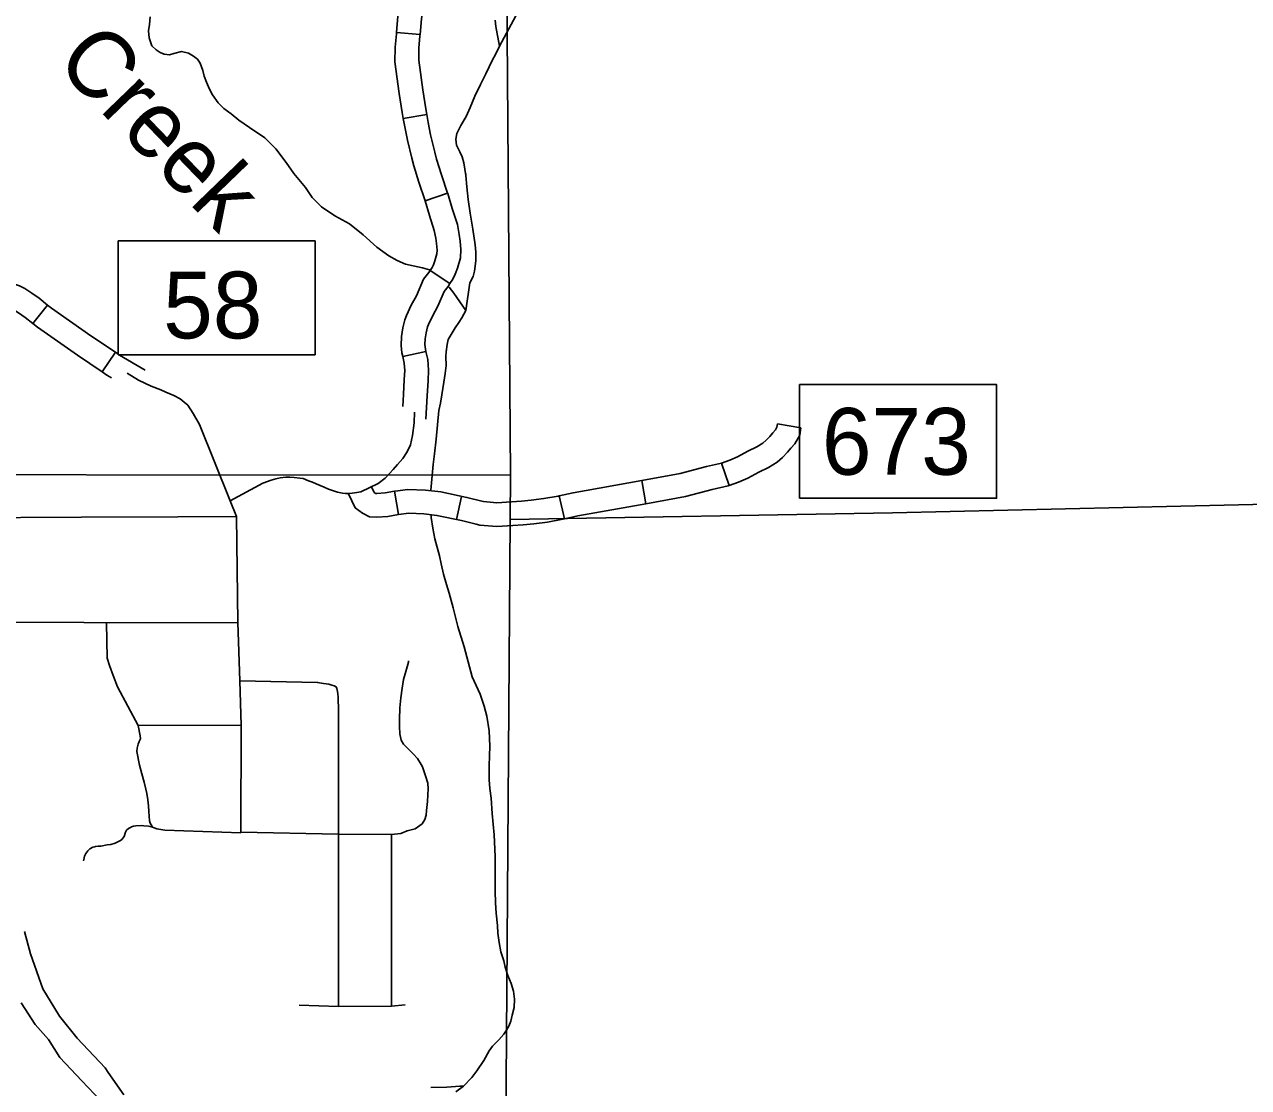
# Model space of a CAD drawing. Extents: x -492261 to -432772, y 1441225 to 1452922.
# Drawn here: x -463423.9 to -463202.9, y 1451379.2 to 1451571.3 of the extents above; entities that cross this region are included whole.
import ezdxf

# ---------------------------------------------------------------- set-up
doc = ezdxf.new("R2010")
doc.units = 0
doc.layers.add('Default', color=7, linetype='Continuous')

msp = doc.modelspace()

# ---------------------------------------------------------------- linework, layer by layer
at = {"layer": 'Default'}
for p, q in [((-463356.77, 1451569.8), (-463352.5, 1451569.45)), ((-463355.53, 1451554.3), (-463351.3, 1451555.02)), ((-463351.59, 1451539.42), (-463347.52, 1451540.77)), ((-463350.66, 1451526.83), (-463347.1, 1451524.46)), ((-463422.45, 1451517.23), (-463419.76, 1451520.57)), ((-463409.93, 1451508.5), (-463407.53, 1451512.05)), ((-463355.62, 1451511.27), (-463351.44, 1451512.2)), ((-463287.93, 1451499.1), (-463283.7, 1451498.41)), ((-463298.05, 1451492.05), (-463296.65, 1451488)), ((-463312.45, 1451488.91), (-463311.7, 1451484.7)), ((-463357.09, 1451486.95), (-463356.39, 1451482.72)), ((-463344.99, 1451486.02), (-463345.89, 1451481.83)), ((-463327.37, 1451486.12), (-463326.43, 1451481.94))]:
    msp.add_line(p, q, dxfattribs=at)
for points in [[(-463339.09, 1451740.72), (-463337.5, 1451641.25), (-463337.22, 1451633.29), (-463336.18, 1451489.83), (-463336.25, 1451481.82), (-463337.26, 1451337.74), (-463337.04, 1451330.58), (-463339.5, 1451167.68)], [(-463352.57, 1451584.76), (-463353.12, 1451583.25), (-463353.82, 1451581.65), (-463354.9, 1451579.19), (-463355.69, 1451577.12), (-463356.24, 1451574.87), (-463356.53, 1451572.75), (-463356.77, 1451569.8)], [(-463348.55, 1451583.28), (-463349.14, 1451581.66), (-463349.89, 1451579.93), (-463350.93, 1451577.56), (-463351.59, 1451575.84), (-463352.02, 1451574.07), (-463352.26, 1451572.29), (-463352.5, 1451569.45)], [(-463346.02, 1451550.55), (-463345.85, 1451551.57), (-463345.12, 1451553), (-463344.17, 1451554.67), (-463343.45, 1451556.28), (-463342.61, 1451558.35), (-463341.61, 1451560.42), (-463340.6, 1451562.38), (-463340.04, 1451563.65), (-463339.54, 1451564.62), (-463338.76, 1451566.12), (-463338.14, 1451567.33), (-463335.18, 1451572.85), (-463333.61, 1451575.22), (-463331.63, 1451577.53), (-463330, 1451579.09), (-463328.75, 1451579.96), (-463326.82, 1451580.79), (-463324.37, 1451581.22), (-463322.1, 1451581.76), (-463320.22, 1451582.01)], [(-463350.81, 1451526.94), (-463352.04, 1451527.3), (-463353.76, 1451527.68), (-463355.13, 1451527.95), (-463356.62, 1451528.62), (-463358.11, 1451529.46), (-463360.29, 1451531.03), (-463362.77, 1451533.3), (-463365.24, 1451535.27), (-463367.88, 1451536.73), (-463370.29, 1451538.3), (-463371.97, 1451540), (-463373.18, 1451541.82), (-463375.32, 1451544.37), (-463376.71, 1451546.35), (-463378.56, 1451548.79), (-463380.52, 1451550.77), (-463383.33, 1451552.69), (-463385.23, 1451553.98), (-463386.61, 1451555.11), (-463387.93, 1451556.07), (-463388.97, 1451557.14), (-463390.01, 1451558.56), (-463390.53, 1451559.58), (-463391.06, 1451560.84), (-463391.47, 1451561.92), (-463391.71, 1451562.95), (-463392.24, 1451564.26), (-463392.7, 1451564.99), (-463393.39, 1451565.56), (-463394.31, 1451566.12), (-463395.57, 1451566.39), (-463396.99, 1451566.03), (-463397.73, 1451565.79), (-463398.7, 1451565.9), (-463399.44, 1451566.23), (-463400.19, 1451566.68), (-463400.94, 1451567.42), (-463401.41, 1451568.84), (-463401.54, 1451570.1), (-463401.38, 1451571.25), (-463401.22, 1451572.68)], [(-463338.14, 1451567.33), (-463338.81, 1451570.93), (-463338.93, 1451572.07)], [(-463356.77, 1451569.8), (-463356.78, 1451569.61), (-463356.99, 1451567.19), (-463357.03, 1451564.55), (-463356.26, 1451558.83), (-463355.71, 1451555.36), (-463355.53, 1451554.3)], [(-463352.5, 1451569.45), (-463352.51, 1451569.25), (-463352.71, 1451566.98), (-463352.74, 1451564.81), (-463352.02, 1451559.45), (-463351.48, 1451556.06), (-463351.3, 1451555.02)], [(-463351.3, 1451555.02), (-463351.06, 1451553.59), (-463350.6, 1451551.33), (-463349.84, 1451548.2), (-463349.5, 1451546.94), (-463348.63, 1451544.09), (-463347.52, 1451540.77)], [(-463355.53, 1451554.3), (-463355.27, 1451552.8), (-463354.78, 1451550.39), (-463353.99, 1451547.13), (-463353.62, 1451545.76), (-463352.71, 1451542.79), (-463351.59, 1451539.42)], [(-463346.02, 1451550.55), (-463345.93, 1451549.49), (-463345.34, 1451548.25), (-463344.89, 1451547.36), (-463344.59, 1451546.26), (-463344.24, 1451544.02)], [(-463342.53, 1451531.45), (-463342.94, 1451534.31), (-463343.43, 1451537.16), (-463343.8, 1451539.68), (-463344.05, 1451541.96), (-463344.24, 1451544.02), (-463344.26, 1451544.27)], [(-463351.59, 1451539.43), (-463350.77, 1451536.76), (-463349.92, 1451534.08), (-463349.66, 1451532.69), (-463349.55, 1451531.7), (-463349.43, 1451530.5), (-463349.46, 1451529.81), (-463349.81, 1451528.57), (-463350.08, 1451527.83), (-463350.3, 1451527.37), (-463350.66, 1451526.83)], [(-463347.52, 1451540.77), (-463347.51, 1451540.74), (-463346.68, 1451538.04), (-463345.76, 1451535.13), (-463345.42, 1451533.33), (-463345.28, 1451532.15), (-463345.14, 1451530.61), (-463345.2, 1451529.12), (-463345.73, 1451527.26), (-463346.13, 1451526.16), (-463346.57, 1451525.24), (-463347.1, 1451524.46)], [(-463407.02, 1451511.61), (-463371.45, 1451511.61), (-463371.45, 1451532.16), (-463407.02, 1451532.16), (-463407.02, 1451511.61)], [(-463343.53, 1451524.6), (-463342.9, 1451525.74), (-463342.65, 1451526.69), (-463342.45, 1451528.57), (-463342.4, 1451530.11), (-463342.53, 1451531.45)], [(-463350.66, 1451526.83), (-463350.9, 1451526.48), (-463351.87, 1451525.29), (-463353.17, 1451522.24), (-463354.1, 1451520.54), (-463354.96, 1451518.71), (-463355.24, 1451517.9), (-463355.62, 1451516.45), (-463355.87, 1451514.9), (-463355.93, 1451513.29), (-463355.77, 1451511.93), (-463355.62, 1451511.27)], [(-463435.27, 1451524.75), (-463433.19, 1451524.91), (-463430.62, 1451524.94), (-463429.38, 1451524.89), (-463427.27, 1451524.73), (-463425.94, 1451524.39), (-463424.87, 1451524.05), (-463423.91, 1451523.58), (-463422.64, 1451522.71), (-463421.31, 1451521.82), (-463419.76, 1451520.57)], [(-463347.1, 1451524.46), (-463347.44, 1451523.94), (-463348.16, 1451523.05), (-463349.31, 1451520.36), (-463350.28, 1451518.6), (-463350.98, 1451517.09), (-463351.14, 1451516.64), (-463351.42, 1451515.56), (-463351.6, 1451514.48), (-463351.63, 1451513.46), (-463351.54, 1451512.64), (-463351.44, 1451512.2)], [(-463350.54, 1451487.11), (-463350.54, 1451487.15), (-463350.34, 1451489.78), (-463350.13, 1451491.79), (-463349.87, 1451493.68), (-463349.61, 1451496.37), (-463349.09, 1451501.53), (-463348.82, 1451502.85), (-463348.55, 1451504.39), (-463348.18, 1451506.63), (-463347.97, 1451508.23), (-463347.81, 1451509.67), (-463347.83, 1451511.27), (-463347.78, 1451512.13), (-463347.62, 1451513.44), (-463347.4, 1451514.36), (-463346.17, 1451516.49), (-463345.49, 1451517.41), (-463344.93, 1451518.28), (-463344.21, 1451519.6), (-463343.53, 1451524.6)], [(-463344.21, 1451519.6), (-463346.41, 1451522.73), (-463347.27, 1451523.81)], [(-463434.93, 1451520.48), (-463433, 1451520.63), (-463430.67, 1451520.66), (-463429.63, 1451520.62), (-463427.97, 1451520.48), (-463427.12, 1451520.27), (-463426.48, 1451520.06), (-463426.07, 1451519.86), (-463425.04, 1451519.16), (-463423.84, 1451518.36), (-463422.45, 1451517.23)], [(-463419.76, 1451520.57), (-463419.05, 1451520), (-463411.94, 1451515.04), (-463407.53, 1451512.05)], [(-463422.45, 1451517.23), (-463421.62, 1451516.57), (-463414.36, 1451511.51), (-463409.93, 1451508.5)], [(-463407.53, 1451512.05), (-463406.78, 1451511.54), (-463402.13, 1451508.81)], [(-463355.62, 1451511.27), (-463355.36, 1451510.08), (-463355.25, 1451508.77), (-463355.34, 1451507.14), (-463355.48, 1451504.4), (-463355.6, 1451502.24)], [(-463351.44, 1451512.2), (-463351.11, 1451510.73), (-463350.96, 1451508.83), (-463351.06, 1451506.92), (-463351.2, 1451504.17), (-463351.44, 1451499.99)], [(-463409.93, 1451508.5), (-463409.07, 1451507.91), (-463408.22, 1451507.42)], [(-463405.41, 1451508.25), (-463403.33, 1451507.03), (-463401.04, 1451505.91), (-463399.32, 1451505.25), (-463398.41, 1451504.86), (-463396.97, 1451504.24), (-463395.83, 1451503.63), (-463395.08, 1451503.06), (-463394.45, 1451502.5), (-463393.46, 1451501.02), (-463392.36, 1451499.03), (-463386.79, 1451485.19), (-463385.68, 1451482.4), (-463385.42, 1451463.24), (-463385.03, 1451452.72), (-463384.83, 1451444.71), (-463384.86, 1451425.34)], [(-463283.94, 1451485.68), (-463248.37, 1451485.68), (-463248.37, 1451506.23), (-463283.94, 1451506.23), (-463283.94, 1451485.68)], [(-463386.79, 1451485.19), (-463380.9, 1451488.41), (-463379.42, 1451488.94), (-463378.57, 1451489.18), (-463377.77, 1451489.36), (-463376.74, 1451489.48), (-463376, 1451489.49), (-463375.26, 1451489.44), (-463374.23, 1451489.34), (-463373.6, 1451489.23), (-463372.63, 1451488.84), (-463371.94, 1451488.57), (-463371.26, 1451488.29), (-463369.82, 1451487.68), (-463369.02, 1451487.34), (-463368.16, 1451487.01), (-463367.42, 1451486.79), (-463366.5, 1451486.63), (-463365.99, 1451486.57), (-463365.53, 1451486.52), (-463364.79, 1451486.59), (-463363.94, 1451486.71), (-463363.2, 1451486.84), (-463360.08, 1451488.36), (-463358.83, 1451489.29), (-463357.37, 1451490.85), (-463356.58, 1451491.77), (-463355.62, 1451492.87), (-463354.95, 1451493.91), (-463354.5, 1451494.66), (-463354.22, 1451495.35), (-463353.84, 1451497.01), (-463353.58, 1451499.3), (-463353.5, 1451501.25)], [(-463287.93, 1451499.1), (-463288.03, 1451498.51), (-463288.28, 1451498.06), (-463288.79, 1451497.5), (-463289.32, 1451496.84), (-463289.99, 1451496.16), (-463290.58, 1451495.63), (-463291.64, 1451494.97), (-463293.28, 1451494.18), (-463295.17, 1451493.15), (-463296.54, 1451492.58), (-463298.05, 1451492.05)], [(-463283.7, 1451498.41), (-463283.92, 1451497.05), (-463284.79, 1451495.54), (-463285.52, 1451494.72), (-463286.12, 1451493.99), (-463287.03, 1451493.05), (-463288.02, 1451492.19), (-463289.57, 1451491.21), (-463291.33, 1451490.37), (-463293.3, 1451489.29), (-463295, 1451488.57), (-463296.65, 1451488)], [(-463336.18, 1451489.83), (-463489.43, 1451489.99), (-463536.15, 1451492.48)], [(-463298.05, 1451492.05), (-463298.07, 1451492.04), (-463300.78, 1451491.4), (-463305.5, 1451490.16), (-463312.45, 1451488.91)], [(-463312.45, 1451488.91), (-463324.87, 1451486.69), (-463327.37, 1451486.12)], [(-463356.39, 1451482.72), (-463358.3, 1451482.41), (-463360.31, 1451482.26), (-463361.62, 1451482.35), (-463362.88, 1451482.96), (-463364.21, 1451483.96), (-463365.41, 1451486.51)], [(-463357.09, 1451486.95), (-463358.81, 1451486.67), (-463360.33, 1451486.56), (-463360.5, 1451486.57), (-463360.63, 1451486.63), (-463360.79, 1451486.75), (-463361.26, 1451487.75)], [(-463341.37, 1451485.17), (-463344.04, 1451485.82), (-463348.73, 1451486.82), (-463351.5, 1451487.16), (-463354.73, 1451487.25), (-463356.98, 1451486.97), (-463357.09, 1451486.95)], [(-463327.37, 1451486.12), (-463327.55, 1451486.08), (-463330.13, 1451485.61), (-463332.44, 1451485.31), (-463334.17, 1451485.13), (-463335.96, 1451485.05), (-463338.61, 1451484.86), (-463341.02, 1451485.08), (-463341.37, 1451485.17)], [(-463296.65, 1451488), (-463296.87, 1451487.92), (-463299.74, 1451487.24), (-463304.58, 1451485.97), (-463311.7, 1451484.7)], [(-463311.7, 1451484.7), (-463324.02, 1451482.49), (-463326.43, 1451481.94)], [(-463267.18, 1451483.04), (-463183.84, 1451484.96), (-463033.43, 1451477.86), (-463021.05, 1451477.46)], [(-463385.68, 1451482.4), (-463396.23, 1451482.34), (-463413.63, 1451482.26), (-463435.7, 1451482.12)], [(-463342.38, 1451481), (-463344.99, 1451481.64), (-463349.44, 1451482.59), (-463351.82, 1451482.88), (-463354.52, 1451482.96), (-463356.37, 1451482.73), (-463356.4, 1451482.72)], [(-463344.65, 1451379.49), (-463343.16, 1451381.05), (-463342.26, 1451382.21), (-463340.97, 1451384.11), (-463340.02, 1451385.84), (-463339.4, 1451386.7), (-463338.27, 1451387.86), (-463337.37, 1451388.84), (-463336.86, 1451389.59), (-463336.47, 1451390.28), (-463336.08, 1451391.2), (-463335.86, 1451392.29), (-463335.48, 1451393.67), (-463335.44, 1451395.16), (-463335.62, 1451396.64), (-463336.04, 1451398.01), (-463336.62, 1451399.49), (-463337.1, 1451400.97), (-463337.39, 1451402.11), (-463337.92, 1451403.71), (-463338.23, 1451405.42), (-463338.47, 1451407.14), (-463338.54, 1451408.51), (-463338.74, 1451410.74), (-463338.87, 1451412.62), (-463338.95, 1451414.68), (-463338.96, 1451420.97), (-463339.11, 1451424.86), (-463339.5, 1451428.75), (-463339.64, 1451431.49), (-463339.88, 1451433.26), (-463340.01, 1451434.81), (-463340.04, 1451437.32), (-463339.95, 1451439.16), (-463339.91, 1451440.87), (-463339.99, 1451443.68), (-463340.42, 1451446.3), (-463340.89, 1451448.13), (-463341.66, 1451450.29), (-463343.06, 1451453.42), (-463344.54, 1451458.84), (-463345.66, 1451462.49), (-463346.5, 1451465.91), (-463347.27, 1451468.54), (-463347.74, 1451470.13), (-463348.27, 1451471.96), (-463348.69, 1451473.84), (-463348.99, 1451475.27), (-463349.82, 1451478.35), (-463350.18, 1451480.29), (-463350.49, 1451482.23), (-463350.51, 1451482.66)], [(-463326.43, 1451481.94), (-463326.7, 1451481.88), (-463329.47, 1451481.38), (-463331.94, 1451481.05), (-463333.86, 1451480.85), (-463335.72, 1451480.77), (-463338.65, 1451480.56), (-463341.73, 1451480.84), (-463342.38, 1451481)], [(-463267.18, 1451483.04), (-463336.25, 1451481.82)], [(-463438.33, 1451463.32), (-463413.23, 1451463.26), (-463408.67, 1451463.2), (-463385.42, 1451463.24)], [(-463409.15, 1451463.2), (-463409.03, 1451456.79), (-463408.61, 1451455.48), (-463407.91, 1451453.66), (-463407.15, 1451451.61), (-463403.44, 1451444.65)], [(-463384.86, 1451425.34), (-463367.23, 1451425), (-463357.65, 1451424.94), (-463356, 1451425.13), (-463354.8, 1451425.6), (-463353.38, 1451425.96), (-463352.14, 1451426.89), (-463351.63, 1451427.64), (-463351.41, 1451428.44), (-463351.31, 1451429.3), (-463351.15, 1451430.91), (-463351.11, 1451432.11), (-463351.01, 1451433.2), (-463351.07, 1451434.22), (-463351.49, 1451435.54), (-463351.72, 1451436.1), (-463352.07, 1451437.19), (-463352.31, 1451437.59), (-463352.94, 1451438.67), (-463353.75, 1451439.51), (-463354.73, 1451440.48), (-463355.48, 1451441.27), (-463355.94, 1451441.95), (-463356.18, 1451443.15), (-463356.2, 1451444.46), (-463356.21, 1451445.72), (-463356.18, 1451447.84), (-463355.97, 1451449.62), (-463355.7, 1451451.39), (-463355.49, 1451452.94), (-463355.05, 1451454.37), (-463354.61, 1451456.04), (-463354.61, 1451456.32)], [(-463367.25, 1451393.88), (-463367.23, 1451425), (-463367.24, 1451447.6), (-463367.26, 1451449.43), (-463367.26, 1451449.77), (-463367.32, 1451450.35), (-463367.39, 1451450.74), (-463367.51, 1451451.32), (-463367.68, 1451451.6), (-463368.02, 1451451.82), (-463368.42, 1451451.93), (-463369, 1451452.1), (-463369.91, 1451452.2), (-463371, 1451452.42), (-463385.03, 1451452.72)], [(-463403.44, 1451444.65), (-463403.42, 1451444.61), (-463403.06, 1451442.79), (-463403, 1451442.22), (-463403.22, 1451441.76), (-463403.39, 1451441.24), (-463403.61, 1451440.55), (-463403.66, 1451439.92), (-463403.18, 1451437.47), (-463402.76, 1451435.87), (-463402.35, 1451434.39), (-463402.05, 1451433.13), (-463401.87, 1451432.33), (-463401.69, 1451431.19), (-463401.56, 1451430.1), (-463401.49, 1451429.08), (-463401.36, 1451427.42), (-463401.24, 1451426.96), (-463400.9, 1451426.38)], [(-463384.83, 1451444.71), (-463403.42, 1451444.61)], [(-463400.84, 1451426.28), (-463401.52, 1451426.43), (-463402.36, 1451426.53), (-463402.9, 1451426.56), (-463403.85, 1451426.51), (-463404.28, 1451426.45), (-463404.6, 1451426.33), (-463404.78, 1451426.23), (-463405.16, 1451426.03), (-463405.52, 1451425.71), (-463405.66, 1451425.49), (-463405.72, 1451425.36), (-463405.92, 1451424.57), (-463406.34, 1451424.04), (-463406.63, 1451423.84), (-463407.57, 1451423.35), (-463408.38, 1451423.11), (-463409, 1451423.05), (-463410.14, 1451422.85), (-463410.66, 1451422.8), (-463411.08, 1451422.76), (-463411.16, 1451422.74), (-463411.27, 1451422.73), (-463411.62, 1451422.62), (-463412.13, 1451422.35), (-463412.51, 1451421.96), (-463412.84, 1451421.48), (-463413.12, 1451421.05), (-463413.21, 1451420.42), (-463413.3, 1451420.18)], [(-463400.9, 1451426.38), (-463400.84, 1451426.28), (-463400.55, 1451426.11), (-463400.04, 1451425.95), (-463398.61, 1451425.73), (-463384.86, 1451425.26)], [(-463357.65, 1451424.94), (-463357.67, 1451393.93)], [(-463423.97, 1451407.43), (-463422.89, 1451403.37), (-463420.61, 1451397.08), (-463417.64, 1451392.1), (-463414.45, 1451388.15), (-463409.37, 1451382.77), (-463408.86, 1451381.91), (-463406.01, 1451377.91)], [(-463410.18, 1451376.82), (-463413.6, 1451380.43), (-463417.59, 1451384.66), (-463419.59, 1451387.92), (-463422.04, 1451390.61), (-463424.55, 1451394.5)], [(-463355.16, 1451394.19), (-463357.67, 1451393.93), (-463367.25, 1451393.88), (-463374.32, 1451394.08)], [(-463350.53, 1451379.21), (-463347.68, 1451379.27), (-463345.34, 1451379.49), (-463344.65, 1451379.49), (-463346.02, 1451378.46)]]:
    msp.add_lwpolyline(points, dxfattribs=at)
for points in [[(-463407.02, 1451511.61), (-463371.45, 1451511.61), (-463371.45, 1451532.16), (-463407.02, 1451532.16)], [(-463283.94, 1451485.68), (-463248.37, 1451485.68), (-463248.37, 1451506.23), (-463283.94, 1451506.23)]]:
    msp.add_lwpolyline(points, close=True, dxfattribs=at)

# ---------------------------------------------------------------- texts
msp.add_text('Creek', height=12.069, rotation=314, dxfattribs=at).set_placement((-463418.69, 1451564.24))
for s, p in [('58', (-463398.9, 1451514.56)), ('673', (-463279.92, 1451489.93))]:
    msp.add_text(s, height=12.057, dxfattribs=at).set_placement(p)

doc.saveas('drawing.dxf')
